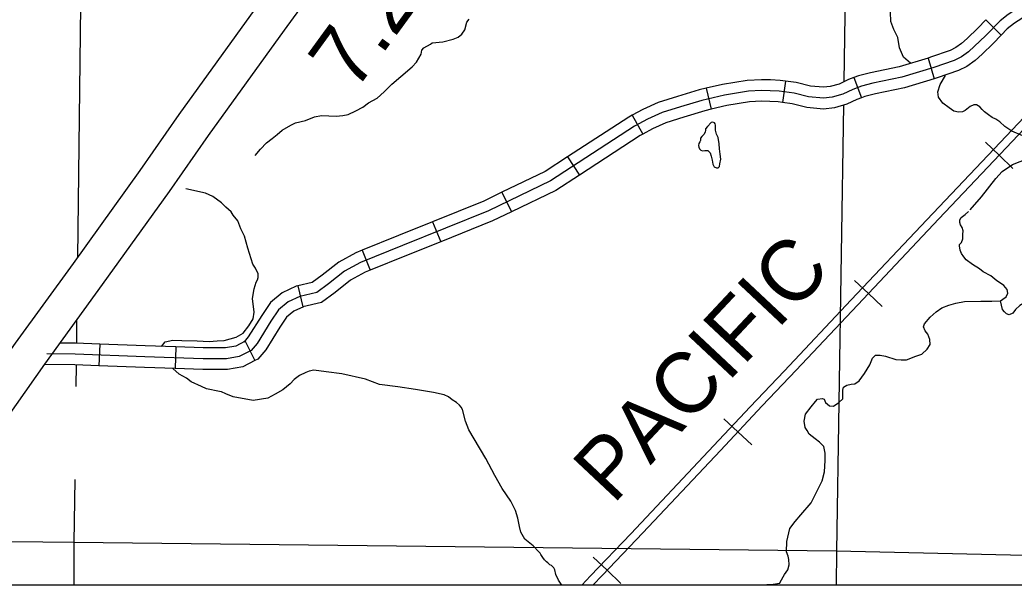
# Model space of a CAD drawing. Extents: x 8749 to 11879, y 13275 to 15339.
# Drawn here: x 9983.2 to 10121.1, y 13439.9 to 13518.3 of the extents above; entities that cross this region are included whole.
import ezdxf

# ---------------------------------------------------------------- set-up
doc = ezdxf.new("R2010")
doc.units = 0
for name, color, linetype in [('Level 15', 7, 'Continuous'), ('Level 32', 7, 'Continuous'), ('Level 35', 7, 'Continuous'), ('Level 40', 7, 'Continuous'), ('Level 46', 7, 'Continuous'), ('Level 48', 7, 'Continuous'), ('Level 5', 7, 'Continuous'), ('R_Draft', 7, 'Continuous')]:
    doc.layers.add(name, color=color, linetype=linetype)

msp = doc.modelspace()

# ---------------------------------------------------------------- linework, layer by layer
at = {"layer": 'Level 15'}
for points in [[(9962.47, 13445.33), (9970.38, 13456.2), (9982.57, 13473.43), (9990.59, 13484.49), (9999.86, 13497.38), (10005.27, 13505.12), (10015.82, 13519.75), (10024.97, 13532.31), (10030.69, 13540.5), (10038.58, 13551.68)], [(9966.51, 13442.39), (9974.44, 13453.28), (9986.63, 13470.52), (9994.64, 13481.56), (10003.94, 13494.48), (10009.35, 13502.22), (10019.87, 13516.82), (10029.04, 13529.41), (10034.79, 13537.62), (10042.67, 13548.8)], [(10062.69, 13439.87), (10064.01, 13441.26), (10069.59, 13447.11), (10080.39, 13458.55), (10086.19, 13464.73), (10090.88, 13469.67), (10100.17, 13479.53), (10110.67, 13490.66), (10120.03, 13500.51), (10126.64, 13507.5), (10129.35, 13510.29), (10132.88, 13513.95), (10137.09, 13518.22), (10141.77, 13523.17), (10147.3, 13528.08), (10150.61, 13530.5)]]:
    msp.add_lwpolyline(points, dxfattribs=at)
at = {"layer": 'Level 32'}
for p, q in [((10117.21, 13518.26), (10119.35, 13516.16)), ((10109.19, 13512.97), (10110.05, 13510.1)), ((10098.89, 13510.25), (10099.95, 13507.44)), ((10078.4, 13508.78), (10079.1, 13505.86)), ((10089.4, 13509.77), (10089, 13506.8)), ((10068.14, 13505.04), (10069.59, 13502.42)), ((10059.17, 13499.26), (10060.81, 13496.74)), ((10050.06, 13494.35), (10051.37, 13491.64)), ((10040.44, 13490.26), (10041.56, 13487.48)), ((10030.64, 13486.31), (10031.76, 13483.53)), ((10021.73, 13481.38), (10022.41, 13478.46)), ((9994.25, 13473.29), (9994.13, 13470.29)), ((10004.8, 13472.9), (10004.69, 13469.9)), ((10014.43, 13473.68), (10015.77, 13471))]:
    msp.add_line(p, q, dxfattribs=at)
for points in [[(10127.87, 13521.57), (10127.18, 13521.18), (10124.48, 13519.75), (10122.86, 13518.87), (10121.18, 13517.79), (10120.19, 13517.01), (10119.35, 13516.16)], [(10117.21, 13518.26), (10116.1, 13517.13), (10114.63, 13515.69), (10113.85, 13514.97), (10113.07, 13514.42), (10112.26, 13514.04), (10109.54, 13513.08), (10109.19, 13512.97)], [(10119.35, 13516.16), (10118.22, 13515.01), (10116.7, 13513.52), (10115.74, 13512.64), (10114.59, 13511.82), (10113.4, 13511.26), (10110.47, 13510.23), (10110.05, 13510.1)], [(10109.19, 13512.97), (10105.17, 13511.76), (10101.2, 13510.93), (10099.53, 13510.49), (10098.89, 13510.25)], [(10089.4, 13509.77), (10088.67, 13509.87), (10087.34, 13509.93), (10086.06, 13509.97), (10084.11, 13509.87), (10080.67, 13509.31), (10078.4, 13508.78)], [(10098.89, 13510.25), (10098.16, 13509.98), (10096.86, 13509.37), (10095.61, 13509.01), (10094.67, 13508.91), (10092.87, 13509.08), (10090.91, 13509.57), (10089.4, 13509.77)], [(10110.05, 13510.1), (10105.91, 13508.86), (10101.89, 13508.01), (10100.44, 13507.63), (10099.95, 13507.44)], [(10078.4, 13508.78), (10077.42, 13508.54), (10074.41, 13507.62), (10071.76, 13506.81), (10069.59, 13505.84), (10068.14, 13505.04)], [(10099.95, 13507.44), (10099.32, 13507.21), (10097.92, 13506.56), (10096.19, 13506.05), (10094.69, 13505.9), (10092.37, 13506.11), (10090.34, 13506.62), (10089, 13506.8)], [(10079.1, 13505.86), (10078.2, 13505.64), (10075.28, 13504.75), (10072.81, 13504), (10070.93, 13503.16), (10069.59, 13502.42)], [(10089, 13506.8), (10088.39, 13506.88), (10087.23, 13506.94), (10086.1, 13506.97), (10084.43, 13506.88), (10081.25, 13506.37), (10079.1, 13505.86)], [(10068.14, 13505.04), (10067.67, 13504.79), (10059.17, 13499.26)], [(10069.59, 13502.42), (10069.22, 13502.21), (10060.81, 13496.74)], [(10059.17, 13499.26), (10056.06, 13497.23), (10050.06, 13494.35)], [(10060.81, 13496.74), (10057.53, 13494.61), (10051.37, 13491.64)], [(10050.06, 13494.35), (10047.56, 13493.14), (10040.44, 13490.26)], [(10051.37, 13491.64), (10048.77, 13490.4), (10041.56, 13487.48)], [(10040.44, 13490.26), (10035.7, 13488.35), (10030.64, 13486.31)], [(10041.56, 13487.48), (10036.82, 13485.57), (10031.76, 13483.53)], [(10030.64, 13486.31), (10029.77, 13485.96), (10027.41, 13484.66), (10025.09, 13482.85), (10023.72, 13481.84), (10021.73, 13481.38)], [(10031.76, 13483.53), (10031.06, 13483.25), (10029.06, 13482.15), (10026.9, 13480.46), (10025, 13479.06), (10022.41, 13478.46)], [(10021.73, 13481.38), (10021.52, 13481.33), (10019.56, 13480.42), (10017.94, 13479.06), (10016.73, 13477.28), (10014.85, 13474.28), (10014.3, 13473.62), (10014.43, 13473.68)], [(10022.5, 13478.48), (10021.18, 13477.86), (10020.18, 13477.03), (10019.24, 13475.64), (10017.29, 13472.52), (10016.2, 13471.21), (10015.77, 13471)], [(9994.25, 13473.29), (9990.88, 13473.42), (9988.75, 13473.44)], [(10004.8, 13472.9), (10000.56, 13473.04), (9994.25, 13473.29)], [(10014.43, 13473.68), (10013.13, 13473.03), (10011.68, 13472.77), (10008.61, 13472.77), (10004.8, 13472.9)], [(9994.13, 13470.29), (9990.8, 13470.42), (9986.59, 13470.46)], [(10004.69, 13469.9), (10000.45, 13470.04), (9994.13, 13470.29)], [(10015.77, 13471), (10014.09, 13470.16), (10011.95, 13469.77), (10008.56, 13469.77), (10004.69, 13469.9)]]:
    msp.add_lwpolyline(points, dxfattribs=at)
at = {"layer": 'Level 35'}
for points in [[(10106.77, 13512.25), (10105.81, 13513.11), (10105.22, 13514.41), (10105.01, 13515.81), (10104.44, 13516.92), (10104.01, 13518.02), (10103.98, 13519.32), (10103.95, 13521.1), (10103.74, 13523.1), (10103.52, 13524.37), (10102.9, 13525.49), (10102.23, 13526.19), (10101.74, 13526.4), (10101.26, 13526.65), (10100.8, 13526.94), (10099.69, 13527.99)], [(10015.8, 13499.44), (10016.53, 13500.34), (10017.39, 13501.2), (10018.17, 13501.79), (10018.85, 13502.36), (10019.57, 13502.98), (10020.76, 13503.66), (10021.43, 13503.98), (10022.81, 13504.33), (10024.05, 13504.84), (10025.02, 13504.98), (10027.04, 13504.92), (10027.96, 13504.98), (10028.72, 13505.14), (10029.77, 13505.63), (10030.74, 13506.14), (10031.52, 13506.76), (10032.76, 13507.41), (10033.73, 13508.3), (10034.76, 13509.35), (10036.02, 13510.4), (10037.61, 13511.75), (10038.18, 13512.39), (10038.85, 13513.52), (10038.96, 13514.06), (10039.2, 13514.39), (10040.12, 13514.9), (10040.36, 13515.09), (10041.85, 13515.2), (10043.28, 13515.58), (10044, 13515.87), (10044.49, 13516.28), (10044.92, 13516.9), (10045.19, 13517.95), (10045.49, 13518.36)], [(10122.35, 13502.17), (10120.84, 13502.82), (10119.87, 13503.47), (10119.17, 13504.14), (10118.6, 13504.49), (10118.09, 13504.74), (10117.58, 13505.09), (10117.04, 13505.49), (10116.71, 13505.84), (10116.39, 13506.22), (10115.9, 13506.49), (10115.53, 13506.46), (10115.04, 13506.27), (10114.34, 13505.68), (10113.96, 13505.49), (10113.4, 13505.46), (10112.77, 13505.6), (10112.13, 13506.06), (10111.24, 13506.71), (10110.64, 13507.54), (10110.54, 13508.3), (10110.89, 13509.3), (10111.62, 13510.57)], [(10078.26, 13500.17), (10078.63, 13500.14), (10078.96, 13499.83), (10079.1, 13499.38), (10079.24, 13498.8), (10079.33, 13498.23), (10079.5, 13497.87), (10079.84, 13497.75), (10080.07, 13497.76), (10080.24, 13497.93), (10080.3, 13498.29), (10080.42, 13498.95), (10080.33, 13499.66), (10080.25, 13500.39), (10080.22, 13501.09), (10080.05, 13501.97), (10079.82, 13502.42), (10079.71, 13502.95), (10079.71, 13503.41), (10079.71, 13503.66), (10079.65, 13503.86), (10079.54, 13503.99), (10079.34, 13504.07), (10079.08, 13504.04), (10078.59, 13503.49), (10078.3, 13503.15), (10078.3, 13502.98), (10078.26, 13502.71), (10078.08, 13502.38), (10077.8, 13502.1), (10077.63, 13501.84), (10077.62, 13501.54), (10077.54, 13501.33), (10077.39, 13501.13), (10077.34, 13500.86), (10077.36, 13500.59), (10077.46, 13500.37), (10077.66, 13500.2), (10077.89, 13500.11), (10078.22, 13500.17)], [(10115.02, 13491.93), (10116.61, 13493.71), (10118.58, 13496.25), (10119.49, 13497.25), (10120.92, 13498.22), (10123.05, 13499.03), (10124.83, 13499.41), (10126.4, 13499.95), (10128.09, 13500.16), (10128.98, 13500.38), (10129.6, 13500.73), (10130.12, 13501.24), (10130.98, 13501.92), (10131.86, 13502.24)], [(10015.48, 13484.38), (10014.81, 13486.62), (10014.34, 13488.28), (10013.82, 13489.27), (10013.4, 13490.4), (10012.74, 13491.2), (10012.46, 13491.63), (10011.75, 13492.29), (10011.13, 13492.91), (10009.95, 13493.76), (10008.92, 13494.23), (10006.18, 13494.84)], [(10089.56, 13444.47), (10089.58, 13445.9), (10089.99, 13447.71), (10090.77, 13448.68), (10091.53, 13449.63), (10092.98, 13451.3), (10093.68, 13452.65), (10094.49, 13454.35), (10094.82, 13455.59), (10094.92, 13457.13), (10094.9, 13458.16), (10094.71, 13459.08), (10094.11, 13459.67), (10093.55, 13460.16), (10092.71, 13460.81), (10092.42, 13461.32), (10092.15, 13461.72), (10092.01, 13462.62), (10092.17, 13463.56), (10092.95, 13464.61), (10093.57, 13465.34), (10093.87, 13465.67), (10094.55, 13465.75), (10094.76, 13465.67), (10094.98, 13465.18), (10095.52, 13464.72), (10096.08, 13464.69), (10096.81, 13465.18), (10097.35, 13465.72), (10097.35, 13466.37), (10097.35, 13466.91), (10097.48, 13467.31), (10097.92, 13467.58), (10098.51, 13467.72), (10099.05, 13467.8), (10099.62, 13468.18), (10100.37, 13469.23), (10101.1, 13470.44), (10101.48, 13471.36), (10101.91, 13471.74), (10102.53, 13471.74), (10103.28, 13471.6), (10104.71, 13471.15), (10105.47, 13471.09), (10106.22, 13471.12), (10107.52, 13471.63), (10108.35, 13471.91), (10109.05, 13472.59), (10109.48, 13473.26), (10109.46, 13473.94), (10109.16, 13474.67), (10108.81, 13475.15), (10108.57, 13475.69), (10108.7, 13476.1), (10109.51, 13477.02), (10110.32, 13477.77), (10111.1, 13478.34), (10112.07, 13478.69), (10113.04, 13478.96), (10114.23, 13479.18), (10116.54, 13479.27), (10118.05, 13479.27), (10119.27, 13479.3), (10119.59, 13479.51), (10120.05, 13479.86), (10120.26, 13480.38), (10120.16, 13480.86), (10119.7, 13481.43), (10119.1, 13481.83), (10118.75, 13482.08), (10117.89, 13482.78), (10116.84, 13483.32), (10116.33, 13483.75), (10115.36, 13484.32), (10114.49, 13484.99), (10114.14, 13485.42), (10113.82, 13485.86), (10113.63, 13486.32), (10113.6, 13486.64), (10113.58, 13486.88), (10113.55, 13487.1), (10113.85, 13487.4), (10114.01, 13487.91), (10114.03, 13488.5), (10114.06, 13489.01), (10113.93, 13489.45), (10113.68, 13489.82), (10113.6, 13490.18), (10113.6, 13490.53), (10113.79, 13490.85), (10114.33, 13491.26), (10114.82, 13491.69)], [(10004.39, 13473.85), (10005.61, 13473.8), (10007.76, 13473.73), (10009.43, 13473.65), (10010.54, 13473.73), (10011.52, 13473.81), (10013.19, 13474.26), (10014.13, 13474.8), (10014.91, 13475.82), (10015.52, 13476.8), (10015.67, 13477.72), (10015.43, 13479.61), (10015.67, 13480.98), (10015.95, 13481.88), (10016.14, 13482.21), (10016.23, 13482.54), (10016.23, 13483.06), (10015.85, 13483.82), (10015.48, 13484.38)], [(10125.72, 13476.29), (10124.64, 13476.21), (10124.07, 13476.23), (10123.72, 13476.45), (10123.48, 13476.61), (10123.27, 13477.02), (10123.21, 13478.04), (10123.16, 13478.61), (10122.78, 13478.91), (10122.4, 13478.91), (10121.94, 13478.66), (10121.35, 13478.1), (10120.95, 13477.58), (10120.46, 13477.37), (10120.08, 13477.48), (10119.81, 13477.75), (10119.54, 13478.1), (10119.27, 13479.3)], [(10002.82, 13472.96), (10003.33, 13473.59), (10004.39, 13473.85)], [(10012.76, 13465.97), (10011.74, 13466.41), (10011.12, 13466.68), (10010.88, 13466.73), (10009.07, 13467.08), (10008.34, 13467.43), (10006.94, 13468.08), (10006.26, 13468.59), (10005.27, 13469.13), (10004.38, 13469.91)], [(10033.05, 13467.67), (10031.11, 13468.42), (10027.82, 13469.15), (10025.66, 13469.45), (10025.66, 13469.45), (10023.96, 13469.67), (10023.29, 13469.53), (10022.86, 13469.37), (10021.94, 13468.94), (10021.24, 13468.37), (10020.65, 13467.8)], [(10020.65, 13467.8), (10019.65, 13466.97), (10018.6, 13466.35), (10017.55, 13465.78), (10015.51, 13465.49), (10012.76, 13465.97)], [(10046.18, 13460.16), (10045.45, 13461.38), (10045, 13462.62), (10044.58, 13464.2), (10044.38, 13464.54), (10044.19, 13464.81), (10043.76, 13465.21), (10043.16, 13465.56), (10042.65, 13465.97), (10042.06, 13466.27), (10040.55, 13466.56), (10038.07, 13466.99), (10035.61, 13467.37), (10033.05, 13467.67)], [(10055.16, 13444.5), (10054.38, 13445.31), (10053.22, 13446.26), (10052.68, 13447.2), (10052.51, 13448.01), (10052.27, 13449.17), (10051.92, 13450.2), (10051.27, 13451.49), (10050.11, 13453.25), (10049.06, 13455.08), (10047.82, 13457.43), (10046.18, 13460.16)], [(10057.9, 13440.55), (10057.54, 13441.32), (10057.42, 13442), (10057.27, 13442.28), (10056.92, 13442.59), (10056.72, 13442.69), (10056.43, 13442.95), (10056.22, 13443.09), (10055.95, 13443.37), (10055.75, 13443.68), (10055.45, 13444.09), (10055.38, 13444.29), (10055.16, 13444.5)], [(10088.67, 13440.27), (10089.26, 13441.35), (10089.73, 13442), (10089.92, 13442.69), (10089.89, 13443.41), (10089.79, 13443.88), (10089.56, 13444.47)], [(10058.38, 13439.87), (10058.38, 13439.87), (10057.9, 13440.55)], [(10086.78, 13439.87), (10086.87, 13439.93), (10087.72, 13440), (10088.62, 13440.15), (10088.67, 13440.27)]]:
    msp.add_lwpolyline(points, dxfattribs=at)
at = {"layer": 'Level 40'}
for p, q in [((10119.06, 13499.49), (10117.15, 13501.3)), ((10119.06, 13499.49), (10120.97, 13497.67)), ((10100.91, 13480.32), (10098.99, 13482.13)), ((10100.91, 13480.32), (10102.83, 13478.5)), ((10082.79, 13461.11), (10080.87, 13462.92)), ((10082.79, 13461.11), (10084.72, 13459.31)), ((10064.65, 13441.93), (10062.74, 13443.75)), ((10064.65, 13441.93), (10066.56, 13440.11))]:
    msp.add_line(p, q, dxfattribs=at)
msp.add_lwpolyline([(10062.69, 13439.87), (10064.01, 13441.26), (10069.59, 13447.11), (10080.39, 13458.55), (10086.19, 13464.73), (10090.88, 13469.67), (10100.17, 13479.53), (10110.67, 13490.66), (10120.03, 13500.51), (10126.64, 13507.5)], dxfattribs=at)
at = {"layer": 'Level 46'}
for points in [[(10163.26, 13544.72), (10161.96, 13544), (10151.35, 13537.91), (10146.61, 13535.22), (10142.06, 13532.33), (10133.23, 13526.58), (10129.49, 13524.21), (10126.46, 13522.49), (10123.78, 13521.07), (10122.09, 13520.16), (10120.31, 13519.01), (10119.19, 13518.13), (10117.16, 13516.07), (10115.66, 13514.6), (10114.8, 13513.81), (10113.83, 13513.12), (10112.83, 13512.65)], [(10112.83, 13512.65), (10110, 13511.65), (10105.54, 13510.31), (10101.55, 13509.47), (10099.98, 13509.06), (10098.74, 13508.59), (10097.39, 13507.97), (10095.9, 13507.53), (10094.68, 13507.4), (10092.62, 13507.59), (10090.62, 13508.09), (10088.53, 13508.37), (10087.28, 13508.44), (10086.08, 13508.47), (10084.27, 13508.37), (10080.96, 13507.84), (10077.81, 13507.09), (10074.84, 13506.19), (10072.28, 13505.4), (10070.26, 13504.5), (10068.45, 13503.5)], [(10125.01, 13507.41), (10118.38, 13500.4), (10109.02, 13490.55), (10098.51, 13479.42), (10089.23, 13469.56), (10084.53, 13464.61), (10078.72, 13458.43), (10067.94, 13447), (10062.36, 13441.16), (10061.14, 13439.87)], [(10068.45, 13503.5), (10056.8, 13495.92), (10048.17, 13491.77), (10036.26, 13486.96), (10030.42, 13484.61), (10028.23, 13483.4), (10025.99, 13481.65), (10024.36, 13480.45), (10022.01, 13479.9), (10020.37, 13479.14), (10019.06, 13478.05), (10017.98, 13476.46), (10016.07, 13473.4), (10015.25, 13472.41), (10013.61, 13471.59), (10011.81, 13471.27), (10008.59, 13471.27), (10000.51, 13471.54), (9990.84, 13471.92), (9986.89, 13471.95)]]:
    msp.add_lwpolyline(points, dxfattribs=at)
at = {"layer": 'Level 5'}
for points in [[(9991.95, 13551.38), (9991.14, 13485.26)], [(10098.11, 13549.79), (10097.5, 13509.67)], [(10097.45, 13506.42), (10096.51, 13444.58)], [(9991.03, 13476.59), (9991, 13473.42)], [(9990.96, 13470.42), (9990.92, 13467.43)], [(9990.76, 13454.52), (9990.66, 13445.77)], [(9990.66, 13445.77), (9969.14, 13446)], [(10096.51, 13444.58), (9990.66, 13445.77)], [(9990.66, 13445.77), (9990.66, 13439.87)], [(10096.51, 13444.58), (10096.44, 13439.87)], [(10174.94, 13442.76), (10096.51, 13444.58)]]:
    msp.add_lwpolyline(points, dxfattribs=at)
at = {"layer": 'R_Draft'}
msp.add_lwpolyline([(9678.09, 14456.3), (10959.72, 14456.3), (10959.72, 13439.87), (9678.09, 13439.87)], close=True, dxfattribs=at)

# ---------------------------------------------------------------- texts
at = {"layer": 'Level 40'}
msp.add_text('PACIFIC', height=8.448, rotation=46.8433, dxfattribs=at).set_placement((10065.49, 13450.94))
at = {"layer": 'Level 48'}
msp.add_text('7.2', height=8.448, rotation=53.9415, dxfattribs=at).set_placement((10029.59, 13508.11))

doc.saveas('drawing.dxf')
